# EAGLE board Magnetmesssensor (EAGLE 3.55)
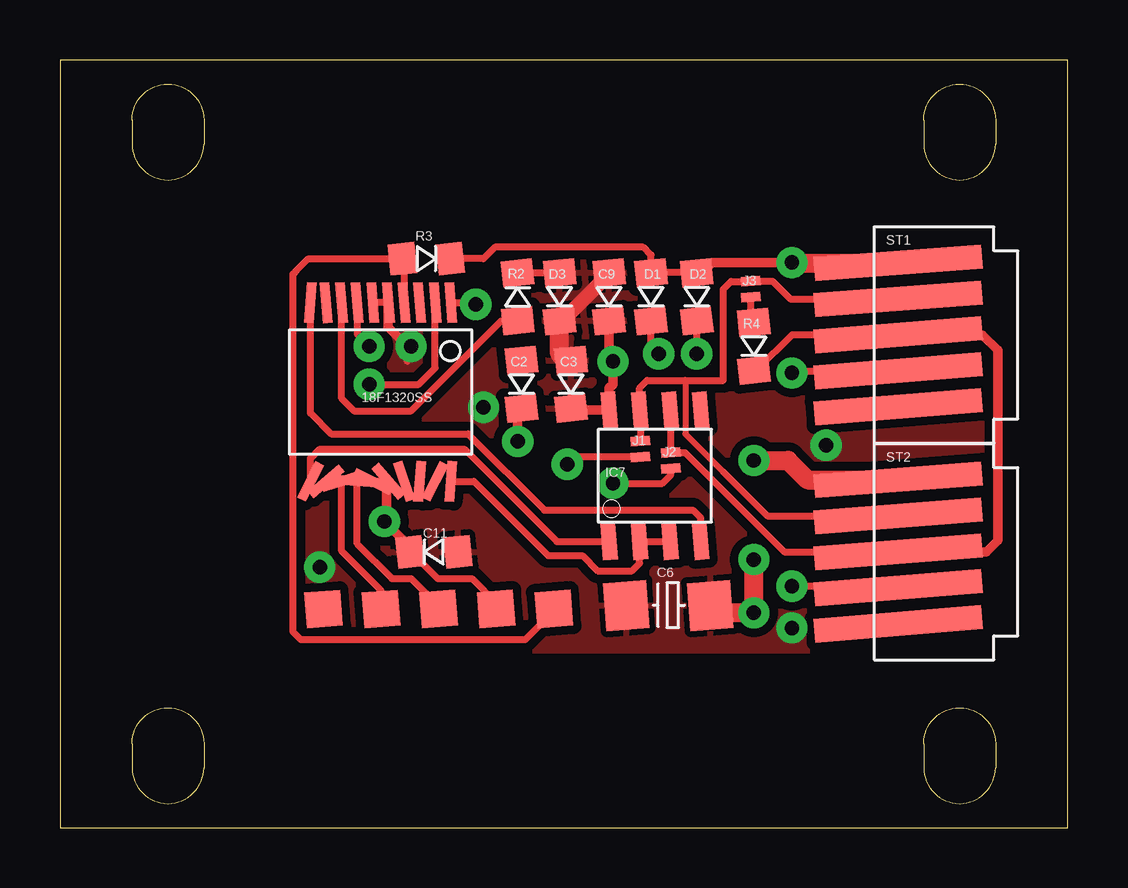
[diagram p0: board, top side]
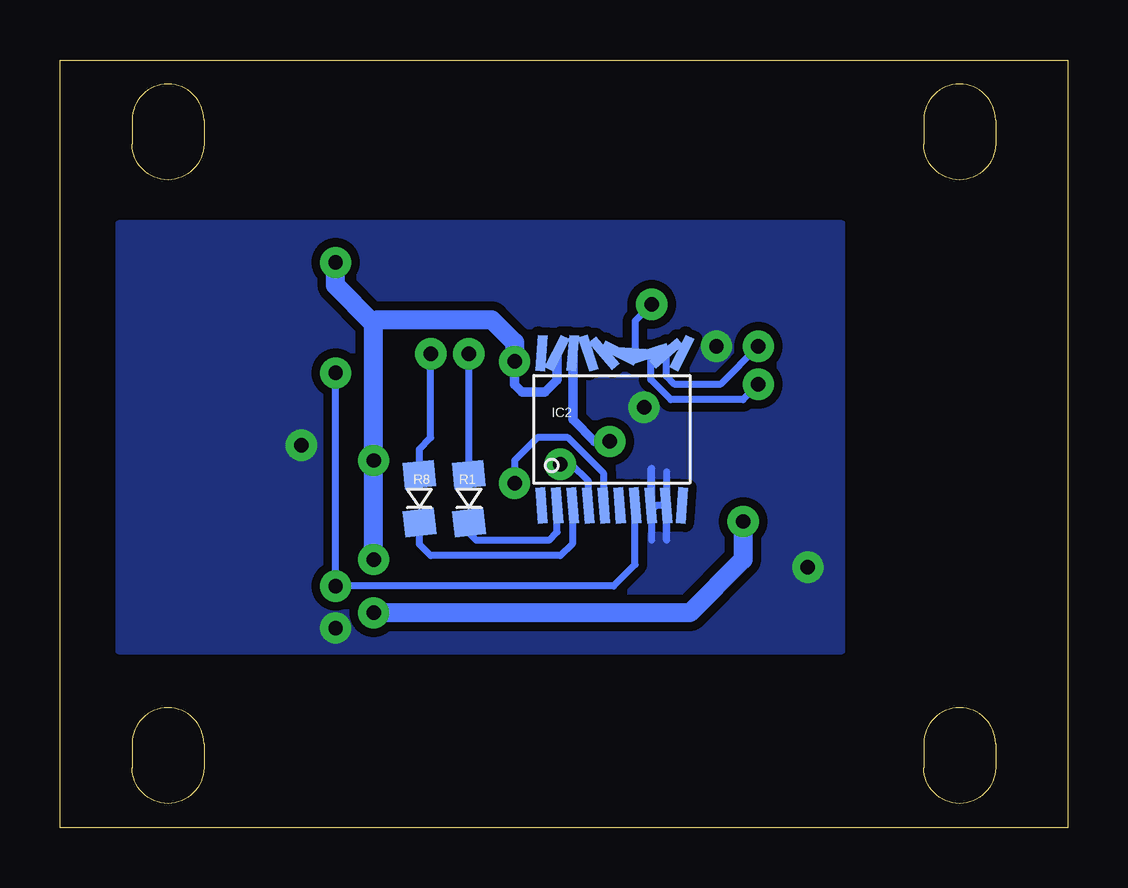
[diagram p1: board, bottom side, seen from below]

Size 42 x 32 mm. Coordinates in mm from the lower left corner, seen from the top.
Outline: 0,0 42,0 42,32 0,32 0,0
Outline: 3,29.5 3,28.5 arc180 6,28.5 6,29.5 arc180 3,29.5
Outline: 3,3.5 3,2.5 arc180 6,2.5 6,3.5 arc180 3,3.5
Outline: 36,3.5 36,2.5 arc180 39,2.5 39,3.5 arc180 36,3.5
Outline: 36,29.5 36,28.5 arc180 39,28.5 39,29.5 arc180 36,29.5
Copper layers used: Top, Bottom

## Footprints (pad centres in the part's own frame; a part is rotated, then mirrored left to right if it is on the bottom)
D0805 = smd 1.1 x 1.3 rotated 5.7:  -1,0 | smd 1.1 x 1.3 rotated 6.6:  1,0
D-ELKA = smd 1.8 x 2 rotated 4.4:  1.824,0.019 | smd 1.8 x 2 rotated 4.3:  -1.676,0.019
OP20_1 = smd 0.4 x 1.7 rotated 4.3:  -2.925,-3.725;  2.925,-3.725 | smd 0.4 x 1.7 rotated 4.4:  -2.275,-3.725;  -2.925,3.725 | smd 0.4 x 1.7 rotated 4.5:  -1.625,-3.725 | smd 0.4 x 1.7 rotated 4.6:  -0.975,-3.725 | smd 0.4 x 1.7 rotated 4.7:  -0.325,-3.725;  0.325,-3.725 | smd 0.4 x 1.7 rotated 4.8:  0.975,-3.725 | smd 0.4 x 1.7 rotated 4.9:  1.625,-3.725 | smd 0.4 x 1.7 rotated 5:  2.275,-3.725 | smd 0.4 x 1.7 rotated 26.8:  2.925,3.725 | smd 0.4 x 1.7 rotated 49.3:  2.275,3.725 | smd 0.4 x 1.7 rotated 71.8:  1.625,3.725 | smd 0.4 x 1.7 rotated 94.3:  0.975,3.725 | smd 0.4 x 1.7 rotated 116.8:  0.325,3.725 | smd 0.4 x 1.7 rotated 139.3:  -0.325,3.725 | smd 0.4 x 1.7 rotated 161.8:  -0.975,3.725 | smd 0.4 x 1.7 rotated 184.3:  -1.625,3.725 | smd 0.4 x 1.7 rotated 206.8:  -2.275,3.725
SOP20 = smd 0.4 x 1.5 rotated 4.3:  -2.925,-3.175;  2.925,-3.175 | smd 0.4 x 1.5 rotated 4.4:  -2.275,-3.175;  -2.925,3.175 | smd 0.4 x 1.5 rotated 4.5:  -1.625,-3.175 | smd 0.4 x 1.5 rotated 4.6:  -0.975,-3.175 | smd 0.4 x 1.5 rotated 4.7:  -0.325,-3.175;  0.325,-3.175 | smd 0.4 x 1.5 rotated 4.8:  0.975,-3.175 | smd 0.4 x 1.5 rotated 4.9:  1.625,-3.175 | smd 0.4 x 1.5 rotated 5:  2.275,-3.175 | smd 0.4 x 1.5 rotated 26.8:  2.925,3.175 | smd 0.4 x 1.5 rotated 49.3:  2.275,3.175 | smd 0.4 x 1.5 rotated 71.8:  1.625,3.175 | smd 0.4 x 1.5 rotated 94.3:  0.975,3.175 | smd 0.4 x 1.5 rotated 116.8:  0.325,3.175 | smd 0.4 x 1.5 rotated 139.3:  -0.325,3.175 | smd 0.4 x 1.5 rotated 161.8:  -0.975,3.175 | smd 0.4 x 1.5 rotated 184.3:  -1.625,3.175 | smd 0.4 x 1.5 rotated 206.8:  -2.275,3.175
8 = smd 0.61 x 1.524 rotated 4.3:  -2.54,-2.743 | smd 0.61 x 1.524 rotated 4.9:  -2.54,2.743 | smd 0.61 x 1.524 rotated 4.4:  -1.27,-2.743 | smd 0.61 x 1.524 rotated 4.5:  0,-2.743 | smd 0.61 x 1.524 rotated 4.8:  -1.27,2.743 | smd 0.61 x 1.524 rotated 4.7:  0,2.743;  1.27,2.743 | smd 0.61 x 1.524 rotated 4.6:  1.27,-2.743
D-J2 = smd 0.4 x 0.8 rotated 4.3:  -0.33,-0.127 | smd 0.4 x 0.8 rotated 4.4:  0.33,-0.127
CP-CON = smd 1.5 x 1.5 rotated 4.3:  0,0 | smd 1.5 x 1.5 rotated 4.4:  -2.4,0 | smd 1.5 x 1.5 rotated 4.5:  -4.8,0 | smd 1.5 x 1.5 rotated 4.6:  -7.2,0 | smd 1.5 x 1.5 rotated 4.7:  -9.6,0
L1,5X5 = smd 1 x 7 rotated 4.3:  -3,-0.5 | smd 1 x 7 rotated 4.4:  -1.5,-0.5 | smd 1 x 7 rotated 4.5:  0,-0.5 | smd 1 x 7 rotated 4.6:  1.5,-0.5 | smd 1 x 7 rotated 4.7:  3,-0.5

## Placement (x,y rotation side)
C2  4,7æ  [D0805]  19.24,18.48 270 top
C3  100n  [D0805]  21.3,18.48 270 top
C6  10æ  [D-ELKA]  25.43,9.27 180 top
C9  100n  [D0805]  22.89,22.13 270 top
C11  100n  [D0805]  15.59,11.49 180 top
D1  Magnitude1  [D0805]  24.64,22.13 270 top
D2  Magnitude2  [D0805]  26.54,22.13 270 top
D3  Power  [D0805]  20.83,22.13 270 top
IC1  18F1320SS  [OP20_1]  13.37,18.16 180 top
IC2  AS5311  [SOP20]  19,16.6 0 bottom
IC7  MAX-485  [8]  25.43,14.67 0 top
J1  SMDJ1  [D-J2]  24.32,15.78 270 top
J2  SMDJ1  [D-J2]  25.59,15.3 270 top
J3  SMDJ1  [D-J2]  28.92,22.45 270 top
JP1  ICSP/Debug  [CP-CON]  10.98,9.11 180 top
R1  1k  [D0805]  24.96,13.71 270 bottom
R2  1k  [D0805]  19.08,22.13 90 top
R3  10k  [D0805]  15.27,23.72 0 top
R4  120R  [D0805]  28.92,20.07 270 top
R8  1k  [D0805]  27.02,13.71 270 bottom
ST1  RS485-2  [L1,5X5]  35.43,20.54 270 top
ST2  RS485-2  [L1,5X5]  35.43,11.49 270 top

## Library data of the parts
C2 C3 C6 C9 C11 D1-D3 IC7 J1-J3 JP1 R1-R4 R8 ST1 ST2 = CONTR1
IC1 = MICROCH
IC2 = sensors

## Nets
+5V: C3. C6. C9. C11. D1. D2. IC1. IC2. IC7. JP1. R3. ST1. ST2.
CSN: IC1. IC2.
GND: C2. C3. C6. C9. C11. D3. IC1. IC2. IC7. JP1. ST1. ST2.
MAGDECN: IC2. R8.
MAGINCN: IC2. R1.
MCLR/: IC1. JP1. R3.
N$2: D1. R1.
N$3: D2. R8.
N$5: D3. R2.
N$9: IC2. J1.
N$10: IC2. J2.
N$16: C2. IC2.
N$24: J3. R4.
O0: IC7. J1. J3. ST1. ST2.
O1: IC7. J2. R4. ST1. ST2.
O2: IC2. ST1. ST2.
PGC: IC1. JP1.
PGD: IC1. JP1.
POWER: IC1. R2.
PWM: IC2.
RXD: IC1. IC7.
SCLK: IC1. IC2.
SDI: IC1. IC2.
TXD: IC1. IC7.
TXEN: IC1. IC7.

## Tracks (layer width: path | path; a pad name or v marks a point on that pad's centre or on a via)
+5V  (via drill 0.6 pad 1.3)
  Top 0.3: 13.69,14.44 13.69,14.5 13.68,14.51 13.61,14.44 13.04,14.44 | C11. 14.64,11.49 15.75,10.38 17.18,10.38 18.18,9.37 18.18,9.11 | R3. 17.65,23.72 18.13,24.19 24.32,24.19 24.64,23.88 24.64,23.13 26.34,23.13 26.38,23.08 26.43,23.13 26.54,23.13
  Top 0.4: 26.54,23.13 26.75,23.13 27.18,23.56 v30.51,23.56 | 13.61,14.44 13.61,12.85 v13.53,12.76 14.59,11.7 C11. | C9. 22.89,19.59 v23.05,19.43 23.05,18.48 22.89,18.32 22.89,17.41 21.51,17.41 21.46,17.37 21.35,17.48 C3.
  Top 0.8: 34.93,23.54 30.69,23.54 v30.51,23.56 | v28.92,11.18 v28.92,8.95 27.02,8.95 26.88,9.25 C6. | 34.93,14.49 31.16,14.49 30.35,15.3 v28.92,15.3
  Bottom 0.4: 21.27,19.77 21.27,18.66 21.78,18.16 22.73,18.16 23.05,18.48 v23.05,19.43
  Bottom 0.8: v30.51,23.56 30.51,22.61 28.92,21.02 | v28.92,11.18 v28.92,15.3 28.92,21.02 | v28.92,8.95 15.75,8.95 13.53,11.18 v13.53,12.76 | v23.05,19.43 23.05,20.22 24,21.18 28.77,21.18 28.92,21.02
CSN  (via drill 0.6 pad 1.3)
  Top 0.3: 16.29,21.89 17.26,21.89 v17.34,21.81
  Bottom 0.3: 18.02,19.77 18.02,21.12 v17.34,21.81
GND  (via drill 0.6 pad 1.3)
  Top 0.3: 13.69,21.89 13.69,21.82 13.68,21.81 13.61,21.89 13.04,21.89 | 14.48,20.07 14.48,19.43
  Top 0.4: 14.48,20.07 | 14.48,20.07 13.68,20.86 13.68,21.81
  Top 0.61: D3. 20.94,21.13 22.89,23.08 22.89,23.13
  Top 0.8: 21.3,19.48 21.1,19.48 20.83,19.75 D3.
  Bottom 0.3: 17.34,11.97 17.34,14.98 17.38,14.95 17.38,13.43 17.2,13.43 17.18,13.4 17.15,13.43 16.73,13.43 16.73,11.99 16.7,11.97 16.7,14.83
  other vias: 17.65,17.52 31.94,15.94 30.51,8.32 10.83,10.86 14.64,20.07
  pour Bottom (isolate 0.356): 9.4,7.37 9.4,25.17 39.56,25.17 39.56,7.37
  pour Top (isolate 0.356): 9.4,7.37 9.4,24.67 39.56,24.67 39.56,7.37
MAGDECN
  Bottom 0.3: 20.62,13.43 20.62,11.85 21.14,11.33 26.54,11.33 27.02,11.81 R8.
MAGINCN
  Bottom 0.3: 21.27,13.43 21.27,12.31 21.62,11.97 24.64,11.97 24.95,12.29 R1.
MCLR/
  Top 0.3: 9.87,23.24 10.35,23.72 14.27,23.72 14.27,23.61 14.34,23.54 14.34,21.89 | 9.87,23.24 | 9.87,23.24 9.71,23.08 9.71,8.16 10.03,7.84 19.4,7.84 20.59,9.03 JP1.
N$2  (via drill 0.6 pad 1.3)
  Top 0.3: D1. 24.64,20.22 24.95,19.91 v24.95,19.75
  Bottom 0.3: 24.95,14.98 | 24.95,14.71 24.95,14.98 | 24.95,14.98 v24.95,19.75
N$3  (via drill 0.6 pad 1.3)
  Top 0.3: D2. v26.54,19.75
  Bottom 0.3: v26.54,19.75 26.54,16.25 27.02,15.78 27.02,14.71
N$5
  Top 0.3: 20.83,23.13 20.72,23.13 20.67,23.08 20.62,23.13 R2.
N$9  (via drill 0.6 pad 1.3)
  Top 0.3: 20.99,14.98 v21.14,15.14 21.46,15.46 24,15.46 24.02,15.45 J1.
  Bottom 0.3: 19.98,13.43 19.98,14.45 20.67,15.14 v21.14,15.14
N$10  (via drill 0.6 pad 1.3)
  Top 0.3: J2. 25.46,14.7 25.11,14.35 v23.05,14.35
  Bottom 0.3: 19.32,13.43 19.32,14.75 20.83,16.25 22.1,16.25 23.05,15.3 v23.05,14.35
N$16  (via drill 0.6 pad 1.3)
  Top 0.4: C2. 19.19,17.48 19.08,17.37 v19.08,16.1
  Bottom 0.4: v19.08,16.1 19.72,16.1 20.62,17 20.62,19.77
N$24
  Top 0.3: 28.92,21.18 | 28.92,21.07 28.92,21.18 | J3. 28.8,21.3 28.92,21.18
O0
  Top 0.254: 27.65,14.83 26.07,16.41 26.07,18.64
  Top 0.3: 24.19,16.11 24.19,17.18 24.16,17.21 24.16,17.41 24.16,18.32 24.48,18.64 26.07,18.64 27.65,18.64 | 34.93,22.04 30.44,22.04 29.7,22.78 28.8,22.78 28.62,22.78 28.61,22.76 27.97,22.76 27.65,22.45 27.65,19.27 27.65,18.64 | 34.93,12.99 29.49,12.99 28.13,14.35 27.65,14.83 | 27.65,18.64 27.65,18.8
O1
  Top 0.3: 25.43,17.41 25.43,17.21 25.46,17.18 25.46,15.63 25.58,15.63 25.59,15.62 26.07,15.62 27.02,14.67 27.5,14.19 30.19,11.49 34.93,11.49 | R4. 29.04,19.07 30.51,20.54 34.93,20.54
  Top 0.4: 39.08,19.91 39.08,11.97 38.61,11.49 34.93,11.49 | 39.08,19.91 | 34.93,20.54 38.45,20.54 39.08,19.91
O2  (via drill 0.6 pad 1.3)
  Top 0.3: 34.93,19.04 30.6,19.04 v30.51,18.95 | 34.93,9.99 34.87,9.99 34.8,10.06 v30.51,10.06
  Bottom 0.3: v30.51,18.95 v30.51,10.06 18.92,10.06 18.02,10.96 18.02,13.43
PGC
  Top 0.3: 13.38,9.11 13.38,9.89 11.74,11.53 11.74,14.44
PGD
  Top 0.3: 12.39,14.44 12.39,11.83 13.84,10.38 14.64,10.38 15.79,9.23 15.79,9.11
POWER
  Top 0.3: 19.08,21.13 18.4,21.13 14.64,17.37 12.26,17.37 11.74,17.88 11.74,21.89
RXD
  Top 0.3: 10.44,14.44 10.44,15.39 10.83,15.78 16.86,15.78 20.71,11.92 22.89,11.92
SCLK  (via drill 0.6 pad 1.3)
  Top 0.3: 15.64,21.89 15.64,19.16 14.95,18.48 v12.89,18.48
  Bottom 0.3: v12.89,18.48 13.53,17.84 16.54,17.84 17.38,18.68 17.38,19.77
SDI  (via drill 0.6 pad 1.3)
  Top 0.3: 12.39,21.89 12.39,20.56 v12.89,20.07
  Bottom 0.3: v12.89,20.07 14.48,18.48 16.38,18.48 16.73,18.82 16.73,19.77
TXD
  Top 0.3: 26.7,11.92 26.7,12.92 26.38,13.24 20.19,13.24 17.02,16.41 11.3,16.41 10.44,17.27 10.44,21.89
TXEN
  Top 0.3: IC1. 17.25,14.44 20.35,11.33 21.78,11.33 22.41,10.7 23.84,10.7 24.16,11.02 24.16,11.92 25.39,11.92 25.43,11.97 25.43,11.92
